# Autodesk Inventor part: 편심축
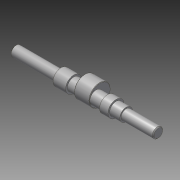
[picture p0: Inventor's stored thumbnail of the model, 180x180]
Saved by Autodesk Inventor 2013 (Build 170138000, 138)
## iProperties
Company: 한국ATC센터
Created: 2014-02
Part Number: 편심축
Document SubType Name: Modeling
Designer: KYOUNG IL JANG
Density: 7.86 g/cm^3
Mass: 246.092 g
Surface Area: 95.1308 cm^2
Volume: 31.3094 cm^3
Material: 강, 연강
Vendor: CBT Solutions
Author: KYOUNG IL JANG
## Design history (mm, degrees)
sketch "스케치1"
  geometry: L1 (-84.5, 0)-(84.5, 0); L2 (-84.5, 0)-(-84.5, 6); L3 (-84.5, 6)-(-30.5, 6); L4 (-30.5, 6)-(-30.5, 9.5); L5 (-30.5, 9.5)-(-15.5, 9.5); L6 (-15.5, 9.5)-(-15.5, 7.5); L7 (-15.5, 7.5)-(46.5, 7.5); L8 (84.5, 6)-(84.5, 0); L9 (34.5, 7.5)-(34.5, 9.5); L10 (34.5, 9.5)-(24.5, 9.5); L11 (24.5, 9.5)-(24.5, 7.5); L12 (46.5, 7.5)-(46.5, 6); L13 (46.5, 6)-(84.5, 6); 2 further points
  constraints: 26 end point, 6 parallel, 6 perpendicular, 2 point on line, 1 coincident, 1 horizontal, 1 midpoint
  dimensions: "d1" = 12 diameter of L3 L1; "d2" = 15 diameter of L7 L1; "d4" = 15 distance of L4.end L5.end; "d5" = 19 diameter of L5 L1; "d24" = 10 distance of L9.end L10.end; "d25" = 19 diameter of L10 L1; "d27" = 40 distance between parallel lines of L11 L6; "d28" = 54 distance of L2.end L3.end; "d29" = 50 distance between parallel lines of L8 L9; "d41" = 38 distance between parallel lines of L8 L12; "d42" = 12 diameter of L13 L1
revolve "회전1" stored, may be unused: angle "d6" = 90 deg
node "작업 평면1"
sketch "스케치2"
  geometry: C1 r 7.5 at (0, 0) reference; C2 r 12.5 at (0, 4.5); 1 further point
  constraints: 1 centre point, 1 vertical alignment
  dimensions: "d8" = 4.5 distance of point (0, 0) C2.centre; "d9" = 25 diameter of C2
extrude "돌출1" join sketch "스케치2" distance "d10" = 18; taper "d11" = 0 deg
chamfer "모따기1" distance "d12" = 1; stored, may be unused: second distance "d13" = 2, angle "d14" = 45 deg
chamfer "모따기2" distance "d15" = 0.5; stored, may be unused: second distance "d16" = 2, angle "d17" = 45 deg
node "작업 평면2"
sketch "스케치3"
  geometry: L1 (4, -2)-(18, -2); L2 (18, 2)-(4, 2); L3 (27, 5)-(27, -5) reference; L4 (-136.5, -2.5)-(-127.5, -2.5); L5 (-127.5, 2.5)-(-136.5, 2.5); L6 (-142, -5)-(-142, 5) reference; A1 r 2 centre (18, 0) between (18, -2) and (18, 2); A2 r 2 centre (4, 0) between (4, 2) and (4, -2); A3 r 2.5 centre (-127.5, 0) between (-127.5, -2.5) and (-127.5, 2.5); A4 r 2.5 centre (-136.5, 0) between (-136.5, 2.5) and (-136.5, -2.5); 2 further points
  constraints: 8 end point, 8 point on circle, 8 tangent, 4 centre point, 2 horizontal, 2 horizontal alignment, 2 parallel, 1 midpoint
  dimensions: "d18" = 7 distance edge to line of A1 L3; "d19" = 4 distance between parallel lines of L2 L1; "d20" = 18 dimension on A1 A2; "d43" = 5 distance between parallel lines of L5 L4; "d44" = 14 dimension on A3 A4; "d45" = 3 distance edge to line of A4 L6
extrude "돌출2" cut sketch "스케치3" distance "d21" = 2.5; taper "d22" = 0 deg
revolve "회전2" stored, may be unused: angle "d26" = 90 deg
node "솔리드1"
other parameters: "d7" = 8.5
